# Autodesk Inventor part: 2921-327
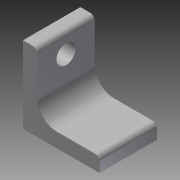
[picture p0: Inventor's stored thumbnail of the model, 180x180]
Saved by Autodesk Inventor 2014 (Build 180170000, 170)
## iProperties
Company: NHTSA/VRTC
Created: 2012-08
Part Number: 2921-327
Material: Steel, Mild
Document SubType Name: Modeling
Designer: Mike Vanvoorhis
Density: 7.86 g/cm^3
Mass: 263.518 g
Surface Area: 94.8417 cm^2
Volume: 33.5264 cm^3
Project: CHILD SIDE IMPACT SLED
Description: D-RING LOWER ANCHOR MTG. ANGLE
Stock Number: L2" x 2" x 3/8" x 38.1mm (1.5")
Appearance: Steel
DESIGN DATE: 2012-11-05
Author: Dave Walker
Title: D-RingLower  Anchor Mtg. Angle
Subject: Child Side Impact Sled
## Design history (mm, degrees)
sketch "Sketch1"
  geometry: L1 (0, 0)-(50.8, 0); L2 (50.8, 0)-(50.8, 9.525); L3 (0, 0)-(0, 50.8); L4 (0, 50.8)-(9.525, 50.8); L5 (9.525, 50.8)-(9.525, 22.225); L6 (22.225, 9.525)-(50.8, 9.525); A1 r 12.7 centre (22.225, 22.225) between (9.525, 22.225) and (22.225, 9.525)
  constraints: 12 end point, 3 parallel, 2 perpendicular, 2 point on circle, 2 tangent, 1 centre point, 1 horizontal
  dimensions: "d0" = 50.8 distance of L1.start L1.end; "d1" = 9.525 distance of L1.end L2.end; "d2" = 50.8 distance of L1.start L3.end; "d3" = 9.525 distance of L3.end L4.end; "d4" = 12.7 radius of A1
extrude "Extrusion1" new body sketch "Sketch1" distance "d5" = 38.1; taper "d6" = 0 deg
sketch "Sketch2"
  geometry: L1 (0, 50.8)-(-38.1, 50.8) reference; L2 (-19.05, 50.8)-(-19.05, 38.1)
  constraints: 2 end point, 1 midpoint, 1 perpendicular
  dimensions: "d7" = 12.7 distance of L2.start L2.end
hole "Hole1" sketch "Sketch2" at (-19.05, 38.1) diameter "d8" = 12.7; stored, may be unused: countersink angle "d12" = 82 deg, drill point angle "d14" = 118 deg; dims "d9" = 19.05, "d10" = 9.525, "d11" = 6.35, "d13" = 25.4
fillet "Fillet1" dims "d15" = 3.175
body "Solid1"
